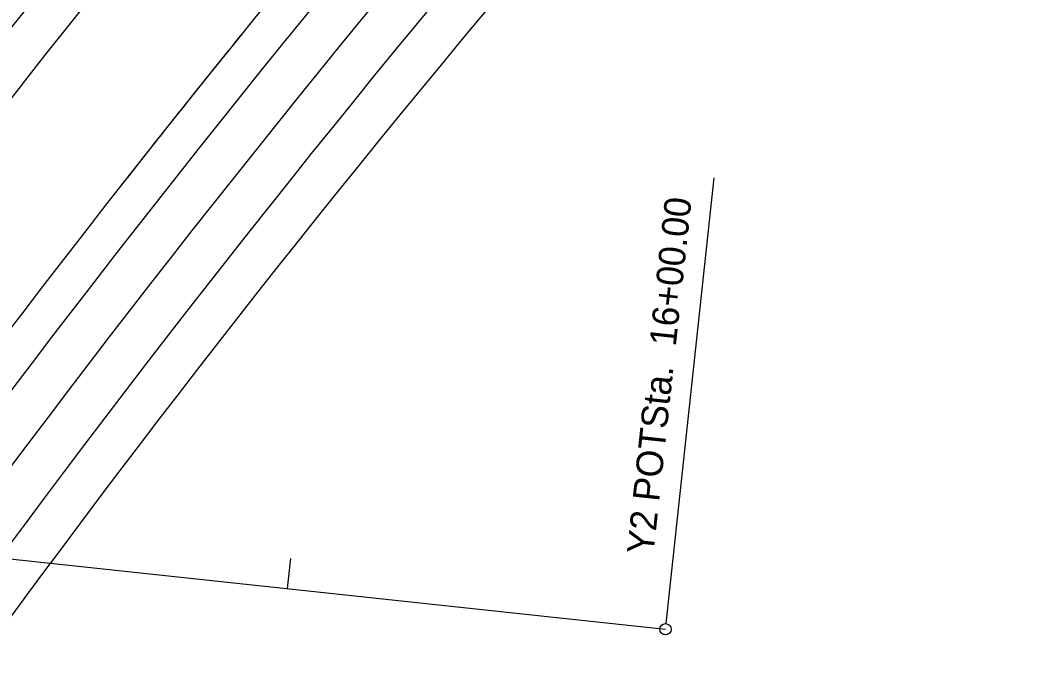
# Model space of a CAD drawing. Extents: x 2389694 to 2405615, y 547005 to 573532.
# Drawn here: x 2395977.9 to 2396240.5, y 557488.1 to 557660.6 of the extents above; entities that cross this region are included whole.
import ezdxf

# ---------------------------------------------------------------- set-up
doc = ezdxf.new("R2010")
doc.units = 0
for name, color, linetype in [('Prop Approach Slab', 7, 'Continuous'), ('Prop Approach Slab Hatching', 7, 'Continuous'), ('Prop EOT', 7, 'Continuous'), ('Prop Horizontal Alignment', 7, 'Continuous'), ('Prop Horizontal Alignment Curve and Spiral Data', 7, 'Continuous'), ('Prop Horizontal Alignment Tick Large', 7, 'Continuous'), ('Prop Lane Lines', 7, 'Continuous')]:
    doc.layers.add(name, color=color, linetype=linetype)

msp = doc.modelspace()

# ---------------------------------------------------------------- linework, layer by layer
at = {"layer": 'Prop Approach Slab'}
for centre, radius, start, end in [((2398729.82, 555480.32), 3571, 139.17799, 149.55348), ((2398605.53, 555570.18), 3358.23, 138.93949, 149.32692), ((2398729.82, 555480.32), 3463, 139.17803, 148.72514), ((2398618.34, 555562.01), 3279.26, 138.98486, 148.54785)]:
    msp.add_arc(centre, radius, start, end, dxfattribs=at)
at = {"layer": 'Prop Approach Slab Hatching'}
msp.add_arc((2398729.82, 555480.32), 3463, 141.05093, 141.96086, dxfattribs=at)
at = {"layer": 'Prop EOT'}
for radius, end in [(3559, 163.17888), (3523, 169.40696), (3453, 155.44499), (3429, 155.44499)]:
    msp.add_arc((2398729.82, 555480.32), radius, 136.54853, end, dxfattribs=at)
at = {"layer": 'Prop Horizontal Alignment'}
msp.add_line((2395551.19, 557564.31), (2396147.75, 557500.12), dxfattribs=at)
msp.add_arc((2398729.82, 555480.32), 3500, 136.54853, 177.15578, dxfattribs=at)
at = {"layer": 'Prop Horizontal Alignment Curve and Spiral Data'}
msp.add_line((2396147.91, 557501.62), (2396160.54, 557618.98), dxfattribs=at)
msp.add_circle((2396147.75, 557500.12), 1.5, dxfattribs=at)
at = {"layer": 'Prop Horizontal Alignment Tick Large'}
msp.add_line((2396048.32, 557510.82), (2396049.18, 557518.78), dxfattribs=at)
at = {"layer": 'Prop Lane Lines'}
for radius, end in [(3547, 169.40696), (3535, 169.40696), (3441, 155.44499)]:
    msp.add_arc((2398729.82, 555480.32), radius, 136.54853, end, dxfattribs=at)

# ---------------------------------------------------------------- texts
at = {"layer": 'Prop Horizontal Alignment Curve and Spiral Data'}
msp.add_text('Y2 POTSta.  16+00.00', height=7, rotation=83.859, dxfattribs=at).set_placement((2396144.57, 557519.59))

doc.saveas('drawing.dxf')
